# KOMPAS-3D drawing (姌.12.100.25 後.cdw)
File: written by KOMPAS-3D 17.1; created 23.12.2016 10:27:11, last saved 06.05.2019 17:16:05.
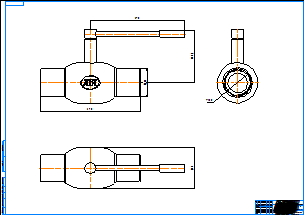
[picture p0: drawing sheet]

Sheet 1: A0, landscape

Title block, sheet 1: name: КШ.12.100.25 сс; material: Внимание! Данный продукт является объектом авторского права ООО «Торговый Дом АДЛ». / Запрещается изменение, копирование, распространение / (в том числе путем копирования на другие сайты и ресурсы в Интернете) / или любое иное использование информации и объектов без предварительного / согласия правообладателя (ООО «Торговый Дом АДЛ»).; sheets: 1; organisation: ООО "Торговый дом АДЛ"; sheet format: A0; stored path: C:\Users\tra\Desktop\2д чертежи\Шаровые краны БИВАЛ\КШ_Бивал_серия_11_12\KOMPAS_2D\КШ.12.100.25 сс.cdw

Views: Вид 1, Проекционный вид 2, Проекционный вид 3
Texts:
  Klimkovich
  ADL
Dimensions and other numbers on the sheet: 390; 108; 370; 205,1; 100; 159; 1:1; 1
